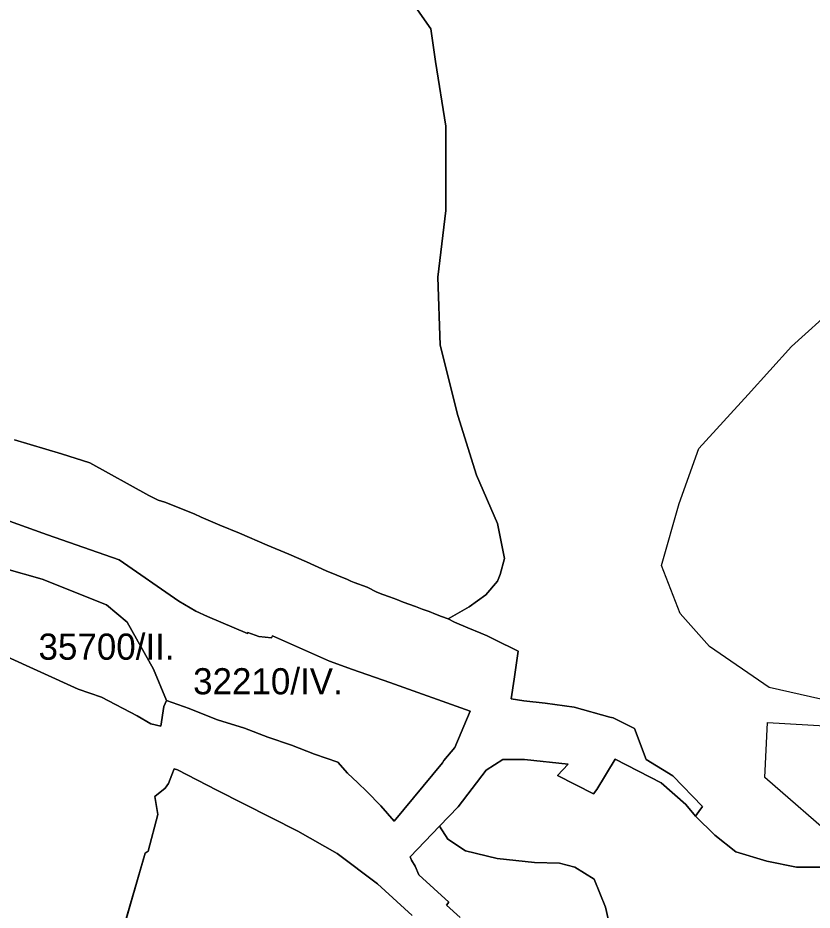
# Model space of a CAD drawing. Extents: x -521621 to -516761, y -1190184 to -1184927.
# Drawn here: x -518666 to -518211, y -1187446 to -1186934 of the extents above; entities that cross this region are included whole.
import ezdxf

# ---------------------------------------------------------------- set-up
doc = ezdxf.new("R2010")
doc.units = 0
doc.layers.add('BPEJ_s', color=7, linetype='Continuous')
doc.layers.add('odvodneni_s', color=7, linetype='Continuous')

msp = doc.modelspace()

# ---------------------------------------------------------------- linework, layer by layer
at = {"layer": 'BPEJ_s'}
for p, q in [((-518668.2, -1187176.14), (-518641.27, -1187184.22)), ((-518641.27, -1187184.22), (-518625.13, -1187189.42)), ((-518625.13, -1187189.42), (-518591.15, -1187208.13)), ((-518591.15, -1187208.13), (-518585.8, -1187210.8)), ((-518585.8, -1187210.8), (-518582.06, -1187211.88)), ((-518582.06, -1187211.88), (-518565.21, -1187218.57)), ((-518652.08, -1187229.66), (-518671.13, -1187222.76)), ((-518565.21, -1187218.57), (-518561.19, -1187220.44)), ((-518561.19, -1187220.44), (-518550.46, -1187225.18)), ((-518550.46, -1187225.18), (-518539.09, -1187229.68)), ((-518649.26, -1187230.68), (-518652.08, -1187229.66)), ((-518608.3, -1187244.95), (-518649.26, -1187230.68)), ((-518539.09, -1187229.68), (-518523.23, -1187236.56)), ((-518523.23, -1187236.56), (-518510.96, -1187241.66)), ((-518510.96, -1187241.66), (-518500.78, -1187246.15)), ((-518574.05, -1187268.63), (-518608.3, -1187244.95)), ((-518500.78, -1187246.15), (-518489.41, -1187251.24)), ((-518489.41, -1187251.24), (-518477.23, -1187256.32)), ((-518477.23, -1187256.32), (-518475.34, -1187257.27)), ((-518475.34, -1187257.27), (-518473.29, -1187258.06)), ((-518473.29, -1187258.06), (-518465.87, -1187260.74)), ((-518465.87, -1187260.74), (-518460.35, -1187263.43)), ((-518460.35, -1187263.43), (-518456.88, -1187264.85)), ((-518564.27, -1187274.45), (-518574.05, -1187268.63)), ((-518456.88, -1187264.85), (-518453.09, -1187266.27)), ((-518453.09, -1187266.27), (-518448.99, -1187267.69)), ((-518448.99, -1187267.69), (-518445.2, -1187269.27)), ((-518445.2, -1187269.27), (-518438.1, -1187271.8)), ((-518557.45, -1187277.54), (-518564.27, -1187274.45)), ((-518438.1, -1187271.8), (-518434.31, -1187273.22)), ((-518434.31, -1187273.22), (-518430.37, -1187274.64)), ((-518534.6, -1187287.31), (-518557.45, -1187277.54)), ((-518430.37, -1187274.64), (-518426.74, -1187276.22)), ((-518426.74, -1187276.22), (-518423.27, -1187277.48)), ((-518423.27, -1187277.48), (-518419.48, -1187278.9)), ((-518419.48, -1187278.9), (-518415.85, -1187280.64)), ((-518415.85, -1187280.64), (-518408.12, -1187283.95)), ((-518408.12, -1187283.95), (-518400.71, -1187287.11)), ((-518534.37, -1187286.74), (-518534.6, -1187287.31)), ((-518527.99, -1187288.9), (-518534.37, -1187286.74)), ((-518520.79, -1187289.73), (-518527.99, -1187288.9)), ((-518520.23, -1187288.6), (-518520.79, -1187289.73)), ((-518487.5, -1187303.07), (-518520.23, -1187288.6)), ((-518400.71, -1187287.11), (-518397.08, -1187288.53)), ((-518397.08, -1187288.53), (-518392.82, -1187290.59)), ((-518392.82, -1187290.59), (-518379.21, -1187297.43)), ((-518674.53, -1187299.62), (-518631.7, -1187319.15)), ((-518379.21, -1187297.43), (-518381.66, -1187313.52)), ((-518474.37, -1187307.86), (-518487.5, -1187303.07)), ((-518452.92, -1187315.38), (-518474.37, -1187307.86)), ((-518406.88, -1187331.85), (-518452.92, -1187315.38)), ((-518381.66, -1187313.52), (-518383.28, -1187324.68)), ((-518631.7, -1187319.15), (-518618.41, -1187323.77)), ((-518618.41, -1187323.77), (-518597.96, -1187334.49)), ((-518383.28, -1187324.68), (-518376.08, -1187325.84)), ((-518584.29, -1187340.34), (-518582.52, -1187329.15)), ((-518582.52, -1187329.15), (-518581.08, -1187325.73)), ((-518581.08, -1187325.73), (-518568.02, -1187330.31)), ((-518568.02, -1187330.31), (-518555.15, -1187335.4)), ((-518376.08, -1187325.84), (-518363.77, -1187327.24)), ((-518363.77, -1187327.24), (-518347.05, -1187329.56)), ((-518347.05, -1187329.56), (-518326.61, -1187335.14)), ((-518597.96, -1187334.49), (-518590.11, -1187339.13)), ((-518555.15, -1187335.4), (-518551.81, -1187336.78)), ((-518415.68, -1187352.64), (-518406.88, -1187331.85)), ((-518326.61, -1187335.14), (-518324.85, -1187335.62)), ((-518324.85, -1187335.62), (-518312.54, -1187341.67)), ((-518590.11, -1187339.13), (-518584.29, -1187340.34)), ((-518551.81, -1187336.78), (-518536.31, -1187341.51)), ((-518536.31, -1187341.51), (-518522.98, -1187346.72)), ((-518312.54, -1187341.67), (-518305.87, -1187359.59)), ((-518522.98, -1187346.72), (-518509.26, -1187351.3)), ((-518509.26, -1187351.3), (-518496.17, -1187356.39)), ((-518496.17, -1187356.39), (-518482.71, -1187361.04)), ((-518421.94, -1187360.16), (-518415.68, -1187352.64)), ((-518482.71, -1187361.04), (-518477.11, -1187367.35)), ((-518450.45, -1187394.81), (-518422.64, -1187361.41)), ((-518422.64, -1187361.41), (-518421.94, -1187360.16)), ((-518388.07, -1187359.56), (-518397.65, -1187365.6)), ((-518375.56, -1187359.56), (-518388.07, -1187359.56)), ((-518350.53, -1187362.26), (-518375.56, -1187359.56)), ((-518323.54, -1187359.27), (-518334.16, -1187376.8)), ((-518297.29, -1187372.85), (-518323.54, -1187359.27)), ((-518305.87, -1187359.59), (-518290.5, -1187368.95)), ((-518576.6, -1187364.85), (-518577.92, -1187368.37)), ((-518574.79, -1187365.41), (-518576.6, -1187364.85)), ((-518552.25, -1187377.02), (-518574.79, -1187365.41)), ((-518397.65, -1187365.6), (-518413.74, -1187386.66)), ((-518356.7, -1187368.61), (-518350.53, -1187362.26)), ((-518577.92, -1187368.37), (-518579.86, -1187373.34)), ((-518477.11, -1187367.35), (-518471.23, -1187372.96)), ((-518336.09, -1187379.3), (-518356.7, -1187368.61)), ((-518290.5, -1187368.95), (-518273.44, -1187386.43)), ((-518581.86, -1187376.01), (-518587.71, -1187380.66)), ((-518579.86, -1187373.34), (-518581.86, -1187376.01)), ((-518471.23, -1187372.96), (-518466.02, -1187377.83)), ((-518334.16, -1187376.8), (-518336.09, -1187379.3)), ((-518283.06, -1187385.33), (-518297.29, -1187372.85)), ((-518587.71, -1187380.66), (-518586, -1187391.15)), ((-518505.78, -1187400.57), (-518552.25, -1187377.02)), ((-518466.02, -1187377.83), (-518458.09, -1187386.18)), ((-518458.09, -1187386.18), (-518450.45, -1187394.81)), ((-518413.74, -1187386.66), (-518424.47, -1187397.86)), ((-518277.49, -1187392.12), (-518283.06, -1187385.33)), ((-518273.44, -1187386.43), (-518275.52, -1187389.38)), ((-518586, -1187391.15), (-518591.57, -1187412.05)), ((-518275.52, -1187389.38), (-518277.49, -1187392.12)), ((-518483.12, -1187413.42), (-518505.78, -1187400.57)), ((-518424.47, -1187397.86), (-518441.19, -1187415.31)), ((-518591.57, -1187412.05), (-518593.3, -1187413.32)), ((-518593.3, -1187413.32), (-518606.43, -1187458.65)), ((-518460.08, -1187430.81), (-518483.12, -1187413.42)), ((-518441.19, -1187415.31), (-518440.44, -1187417.2)), ((-518440.44, -1187417.2), (-518438.4, -1187420.8)), ((-518438.4, -1187420.8), (-518436.21, -1187425.62)), ((-518436.21, -1187425.62), (-518419.15, -1187441.39)), ((-518440.06, -1187448.96), (-518460.08, -1187430.81)), ((-518419.15, -1187441.39), (-518420.46, -1187443.14)), ((-518420.46, -1187443.14), (-518412.59, -1187450.15))]:
    msp.add_line(p, q, dxfattribs=at)
for points in [[(-518450.92, -1186909.41), (-518429.42, -1186940.33), (-518426.74, -1186959.16), (-518420.69, -1186996.13), (-518420.69, -1187044.54), (-518425.39, -1187082.86), (-518424.05, -1187121.85), (-518413.97, -1187162.19), (-518403.22, -1187196.47), (-518391.13, -1187224.04), (-518387.1, -1187244.2), (-518389.55, -1187253.44), (-518391.06, -1187257.16), (-518397.92, -1187265.06), (-518407.32, -1187271.92), (-518419.48, -1187278.9), (-518423.27, -1187277.48), (-518426.74, -1187276.22), (-518430.37, -1187274.64), (-518434.31, -1187273.22), (-518438.1, -1187271.8), (-518445.2, -1187269.27), (-518448.99, -1187267.69), (-518453.09, -1187266.27), (-518456.88, -1187264.85), (-518460.35, -1187263.43), (-518465.87, -1187260.74), (-518473.29, -1187258.06), (-518475.34, -1187257.27), (-518477.23, -1187256.32), (-518489.41, -1187251.24), (-518500.78, -1187246.15), (-518510.96, -1187241.66), (-518523.23, -1187236.56), (-518539.09, -1187229.68), (-518550.46, -1187225.18), (-518561.19, -1187220.44), (-518565.21, -1187218.57), (-518582.06, -1187211.88), (-518585.8, -1187210.8), (-518591.15, -1187208.13), (-518625.13, -1187189.42), (-518641.27, -1187184.22), (-518668.2, -1187176.14)], [(-518195.69, -1187421.38), (-518219.49, -1187421.38), (-518236.54, -1187417.83), (-518254.3, -1187412.5), (-518266.38, -1187402.9), (-518277.49, -1187392.12), (-518275.52, -1187389.38), (-518273.44, -1187386.43), (-518290.5, -1187368.95), (-518305.87, -1187359.59), (-518312.54, -1187341.67), (-518324.85, -1187335.62), (-518326.61, -1187335.14), (-518347.05, -1187329.56), (-518363.77, -1187327.24), (-518376.08, -1187325.84), (-518383.28, -1187324.68), (-518381.66, -1187313.52), (-518379.21, -1187297.43), (-518392.82, -1187290.59), (-518397.08, -1187288.53), (-518400.71, -1187287.11), (-518408.12, -1187283.95), (-518415.85, -1187280.64), (-518419.48, -1187278.9), (-518407.32, -1187271.92), (-518397.92, -1187265.06), (-518391.06, -1187257.16), (-518389.55, -1187253.44), (-518387.1, -1187244.2), (-518391.13, -1187224.04), (-518403.22, -1187196.47), (-518413.97, -1187162.19), (-518424.05, -1187121.85), (-518425.39, -1187082.86), (-518420.69, -1187044.54), (-518420.69, -1186996.13), (-518426.74, -1186959.16), (-518429.42, -1186940.33), (-518450.92, -1186909.41)], [(-518199.64, -1187326.22), (-518235.25, -1187318.15), (-518269.52, -1187294.62), (-518286.31, -1187275.8), (-518297.06, -1187248.24), (-518286.99, -1187212.61), (-518275.56, -1187181.01), (-518247.35, -1187150.08), (-518222.49, -1187122.52), (-518196.96, -1187099.66)], [(-518199.64, -1187326.22), (-518235.25, -1187318.15), (-518269.52, -1187294.62), (-518286.31, -1187275.8), (-518297.06, -1187248.24), (-518286.99, -1187212.61), (-518275.56, -1187181.01), (-518247.35, -1187150.08), (-518222.49, -1187122.52), (-518196.96, -1187099.66)], [(-518671.13, -1187222.76), (-518652.08, -1187229.66), (-518649.26, -1187230.68), (-518608.3, -1187244.95), (-518574.05, -1187268.63), (-518564.27, -1187274.45), (-518557.45, -1187277.54), (-518534.6, -1187287.31), (-518534.37, -1187286.74), (-518527.99, -1187288.9), (-518520.79, -1187289.73), (-518520.23, -1187288.6), (-518487.5, -1187303.07), (-518474.37, -1187307.86), (-518452.92, -1187315.38), (-518406.88, -1187331.85), (-518415.68, -1187352.64), (-518421.94, -1187360.16), (-518422.64, -1187361.41), (-518450.45, -1187394.81), (-518458.09, -1187386.18), (-518466.02, -1187377.83), (-518471.23, -1187372.96), (-518477.11, -1187367.35), (-518482.71, -1187361.04), (-518496.17, -1187356.39), (-518509.26, -1187351.3), (-518522.98, -1187346.72), (-518536.31, -1187341.51), (-518551.81, -1187336.78), (-518555.15, -1187335.4), (-518568.02, -1187330.31), (-518581.08, -1187325.73), (-518588.59, -1187307.67), (-518603.62, -1187280.66), (-518615.58, -1187270.75), (-518652.48, -1187256.04), (-518674.01, -1187249.89)], [(-518674.01, -1187249.89), (-518652.48, -1187256.04), (-518615.58, -1187270.75), (-518603.62, -1187280.66), (-518588.59, -1187307.67), (-518581.08, -1187325.73), (-518582.52, -1187329.15), (-518584.29, -1187340.34), (-518590.11, -1187339.13), (-518597.96, -1187334.49), (-518618.41, -1187323.77), (-518631.7, -1187319.15), (-518674.53, -1187299.62)], [(-518319.17, -1187487.68), (-518329.08, -1187444.28), (-518335.59, -1187428.16), (-518346.74, -1187421.33), (-518355.58, -1187419.01), (-518369.83, -1187418.55), (-518391.36, -1187416.22), (-518409.49, -1187411.88), (-518419.71, -1187405.22), (-518424.47, -1187397.86), (-518413.74, -1187386.66), (-518397.65, -1187365.6), (-518388.07, -1187359.56), (-518375.56, -1187359.56), (-518350.53, -1187362.26), (-518356.7, -1187368.61), (-518336.09, -1187379.3), (-518334.16, -1187376.8), (-518323.54, -1187359.27), (-518297.29, -1187372.85), (-518283.06, -1187385.33), (-518277.49, -1187392.12), (-518266.38, -1187402.9), (-518254.3, -1187412.5), (-518236.54, -1187417.83), (-518219.49, -1187421.38), (-518195.69, -1187421.38)], [(-518606.43, -1187458.65), (-518593.3, -1187413.32), (-518591.57, -1187412.05), (-518586, -1187391.15), (-518587.71, -1187380.66), (-518581.86, -1187376.01), (-518579.86, -1187373.34), (-518577.92, -1187368.37), (-518576.6, -1187364.85), (-518574.79, -1187365.41), (-518552.25, -1187377.02), (-518505.78, -1187400.57), (-518483.12, -1187413.42), (-518460.08, -1187430.81), (-518440.06, -1187448.96)], [(-518412.59, -1187450.15), (-518420.46, -1187443.14), (-518419.15, -1187441.39), (-518436.21, -1187425.62), (-518438.4, -1187420.8), (-518440.44, -1187417.2), (-518441.19, -1187415.31), (-518424.47, -1187397.86), (-518419.71, -1187405.22), (-518409.49, -1187411.88), (-518391.36, -1187416.22), (-518369.83, -1187418.55), (-518355.58, -1187419.01), (-518346.74, -1187421.33), (-518335.59, -1187428.16), (-518329.08, -1187444.28), (-518319.17, -1187487.68)]]:
    msp.add_lwpolyline(points, dxfattribs=at)
at = {"layer": 'odvodneni_s'}
msp.add_lwpolyline([(-518195.14, -1187407), (-518237.7, -1187369.82), (-518236.16, -1187338.27), (-518199.87, -1187340.38), (-518173.8, -1187344.62), (-518113.74, -1187347.57), (-518081.32, -1187351.71), (-518067.11, -1187359.78)], dxfattribs=at)

# ---------------------------------------------------------------- texts
at = {"layer": 'BPEJ_s'}
for s, p in [('35700/II.', (-518654.5, -1187302.28)), ('32210/IV.', (-518565.79, -1187322.13))]:
    msp.add_text(s, height=15, dxfattribs=at).set_placement(p)

doc.saveas('drawing.dxf')
